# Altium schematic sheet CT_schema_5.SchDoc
size 368 x 336 mm
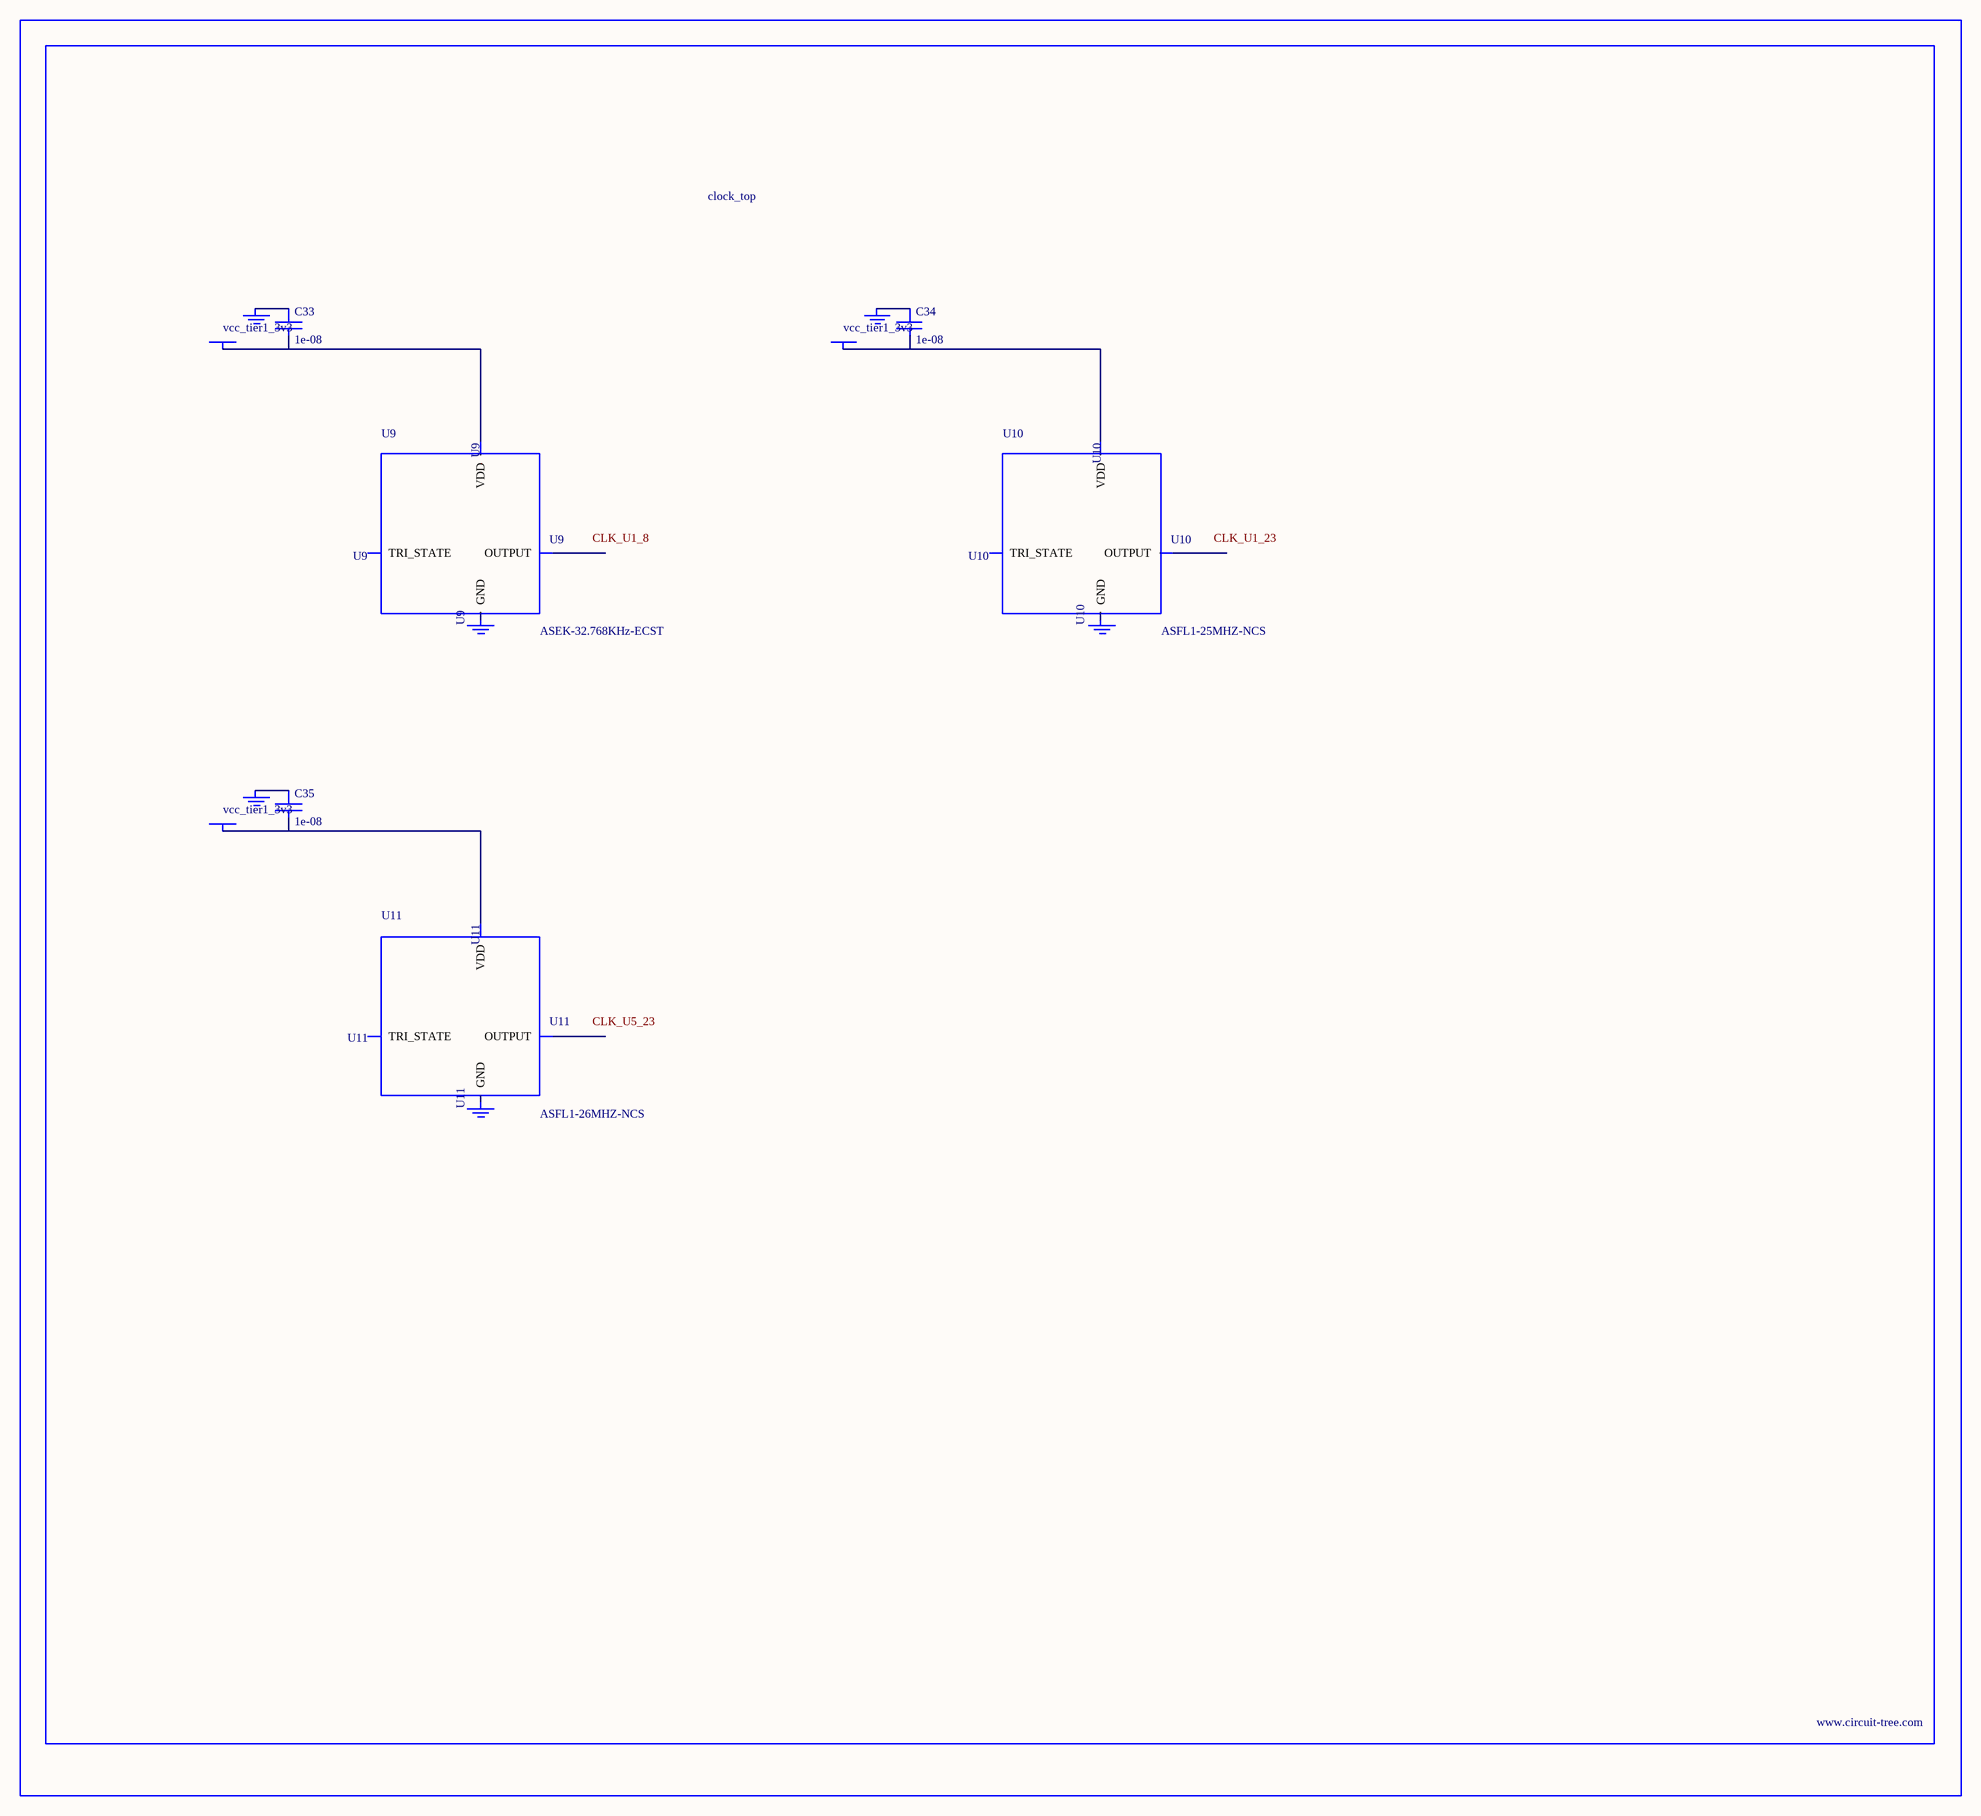
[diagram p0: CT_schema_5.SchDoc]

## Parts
BORDER4  (no value)
C33  1e-08  [C0402]
C34  1e-08  [C0402]
C35  1e-08  [C0402]
GND_INSTANCE_4_0  (no value)
GND_INSTANCE_4_1  (no value)
GND_INSTANCE_4_2  (no value)
GND_INSTANCE_4_3  (no value)
GND_INSTANCE_4_4  (no value)
GND_INSTANCE_4_5  (no value)
POWER_INSTANCE_4_0  vcc_tier1_3v3
POWER_INSTANCE_4_1  vcc_tier1_3v3
POWER_INSTANCE_4_2  vcc_tier1_3v3
U9  ASEK-32.768KHz-ECST  [ASEK]
U10  ASFL1-25MHZ-NCS  [ASFL1]
U11  ASFL1-26MHZ-NCS  [ASFL1]

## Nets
NetC33_1: C33.1 GND_INSTANCE_4_0.0(GND)
NetC33_2: C33.2 POWER_INSTANCE_4_0.0(PWR) U9.4(VDD)
NetC34_1: C34.1 GND_INSTANCE_4_2.0(GND)
NetC34_2: C34.2 POWER_INSTANCE_4_1.0(PWR) U10.4(VDD)
NetC35_1: C35.1 GND_INSTANCE_4_4.0(GND)
NetC35_2: C35.2 POWER_INSTANCE_4_2.0(PWR) U11.4(VDD)

Not connected (* = marked no-connect by the designer): GND_INSTANCE_4_1 0(GND); GND_INSTANCE_4_3 0(GND); GND_INSTANCE_4_5 0(GND); U9 1(TRI_STATE) 2(GND) 3(OUTPUT); U10 1(TRI_STATE) 2(GND) 3(OUTPUT); U11 1(TRI_STATE) 2(GND) 3(OUTPUT)

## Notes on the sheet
- Labels drawn without touching a wire or pin: CLK_U1_8, CLK_U1_23, CLK_U5_23

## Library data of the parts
BORDER4 = BORDER_PAGE4
C33-C35 = C0402C103K3RAC
GND_INSTANCE_4_0-GND_INSTANCE_4_5 = GND
POWER_INSTANCE_4_0-POWER_INSTANCE_4_2 = PWR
